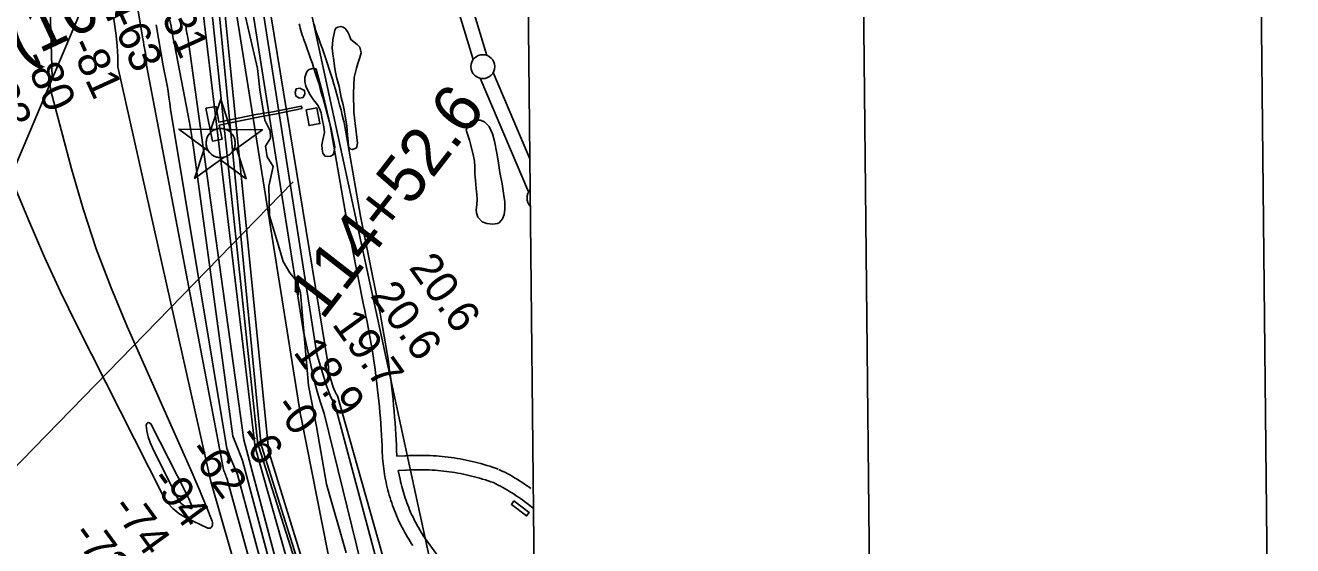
# Model space of a CAD drawing. Extents: x 3625074 to 3663148, y 511451 to 537151.
# Drawn here: x 3659909 to 3662565, y 517810 to 518899 of the extents above; entities that cross this region are included whole.
import ezdxf

# ---------------------------------------------------------------- set-up
doc = ezdxf.new("R2010")
doc.units = 0
for name, color, linetype in [('G-ANNO-NPLT', 7, 'Continuous'), ('V-ANNO-SYMB', 7, 'Continuous'), ('V-BLDG-OTLN', 7, 'Continuous'), ('V-CHAN-DOCK', 7, 'Continuous'), ('V-CHAN-NAID', 7, 'Continuous'), ('V-GRID-FRAM', 7, 'Continuous'), ('V-RIVR-EDGE', 7, 'Continuous'), ('V-RIVR-RANG', 7, 'Continuous'), ('V-ROAD-CNTR', 7, 'Continuous'), ('V-SITE-VEGE', 7, 'Continuous'), ('V-SURV-IDEN', 7, 'Continuous'), ('V-SURV-LINE', 7, 'Continuous'), ('V-TOPO-DPTH', 7, 'Continuous'), ('V-TOPO-MAJR', 7, 'Continuous'), ('V-TOPO-MINR', 7, 'Continuous'), ('V-TOPO-WATR', 7, 'Continuous'), ('V-UTIL-LINE', 7, 'Continuous')]:
    doc.layers.add(name, color=color, linetype=linetype)

msp = doc.modelspace()

# ---------------------------------------------------------------- linework, layer by layer
at = {"layer": 'G-ANNO-NPLT'}
msp.add_lwpolyline([(3625900.3, 512034), (3662565.2, 512401.9), (3662322.6, 536567.4), (3625657.8, 536199.4)], close=True, dxfattribs=at)
at = {"layer": 'V-ANNO-SYMB'}
msp.add_lwpolyline([(3628644.1, 512686.6), (3661725.6, 513018.6), (3661495.6, 535934), (3628414.1, 535602), (3628644.1, 512686.6)], dxfattribs=at)
at = {"layer": 'V-BLDG-OTLN'}
for points in [[(3660491.7, 518748.4), (3660483, 518746.4), (3660476.1, 518751.4), (3660474.6, 518758.4), (3660476.9, 518766), (3660485, 518768), (3660494.1, 518763), (3660495.2, 518756)], [(3660520.3, 518726.6), (3660526.7, 518693.6), (3660504.2, 518689.3), (3660497.8, 518722.3)], [(3660933.4, 517903.4), (3660965.3, 517879.1), (3660959.8, 517871.9), (3660927.9, 517896.2)]]:
    msp.add_lwpolyline(points, close=True, dxfattribs=at)
at = {"layer": 'V-CHAN-DOCK'}
msp.add_lwpolyline([(3660489.7, 518724.9), (3660432.5, 518713.4), (3660408.1, 518709.1), (3660370, 518701.4), (3660315.7, 518689.9), (3660321.7, 518660.7), (3660301.5, 518656.9), (3660287.8, 518725.5), (3660309.3, 518729.2), (3660314.6, 518696.5), (3660392.7, 518712.3), (3660428.4, 518718.2), (3660487.5, 518730.2), (3660489.7, 518724.9)], dxfattribs=at)
at = {"layer": 'V-CHAN-NAID'}
for points in [[(3660307.8, 518681.3), (3660298.2, 518681.4), (3660319.3, 518744.9), (3660339.5, 518681.1), (3660330, 518681.2), (3660328.4, 518681.8), (3660326.3, 518682.4), (3660324.2, 518682.8), (3660322.2, 518683.1), (3660321, 518683.3), (3660319.5, 518683.3), (3660317.8, 518683.3), (3660316.4, 518683.3), (3660314.5, 518683.1), (3660313.1, 518682.8), (3660311.4, 518682.5), (3660309.8, 518682), (3660308.8, 518681.7)], [(3660307.8, 518681.3), (3660231.3, 518681.9), (3660292.9, 518636.5), (3660291.7, 518638.4), (3660290.9, 518640), (3660290.1, 518642), (3660289.4, 518644), (3660289, 518645.4), (3660288.7, 518647), (3660288.4, 518648.4), (3660288.2, 518650), (3660288.1, 518651.8), (3660288.1, 518653.3), (3660288.2, 518655.4), (3660288.4, 518657), (3660288.8, 518659.2), (3660289.3, 518661.2), (3660289.9, 518663.1), (3660290.6, 518664.7), (3660291.3, 518666.3), (3660292.1, 518667.9), (3660293.2, 518669.6), (3660294.2, 518671.1), (3660295.2, 518672.3), (3660296.2, 518673.5), (3660297.5, 518674.8), (3660298.5, 518675.8), (3660300.3, 518677.2), (3660301.5, 518678), (3660303.2, 518679.1), (3660304.9, 518680.1), (3660306.3, 518680.7)], [(3660330, 518681.2), (3660406.4, 518680.6), (3660344.2, 518636.1), (3660345.2, 518637.6), (3660346.1, 518639.5), (3660346.8, 518641), (3660347.6, 518643), (3660348.1, 518644.8), (3660348.5, 518646.4), (3660348.9, 518648.4), (3660349.1, 518650), (3660349.2, 518652.2), (3660349.2, 518654.3), (3660349, 518656.5), (3660348.7, 518658.2), (3660348.2, 518660.5), (3660347.6, 518662.6), (3660346.8, 518664.6), (3660346.2, 518666), (3660345.2, 518668), (3660344.1, 518669.7), (3660342.9, 518671.4), (3660341.6, 518672.9), (3660340.4, 518674.3), (3660338.7, 518675.8), (3660337, 518677.2), (3660335.3, 518678.4), (3660333.4, 518679.5), (3660332, 518680.3)], [(3660326.2, 518623.2), (3660264, 518578.7), (3660285.1, 518642.2), (3660292.9, 518636.5), (3660293.5, 518635.5), (3660294.9, 518633.7), (3660296.1, 518632.2), (3660297.5, 518630.7), (3660298.9, 518629.5), (3660300.4, 518628.3), (3660301.8, 518627.3), (3660303.5, 518626.3), (3660305.2, 518625.4), (3660307, 518624.6), (3660308.4, 518624), (3660310.1, 518623.5), (3660312.3, 518622.9), (3660313.8, 518622.7), (3660315.8, 518622.4), (3660317.4, 518622.3), (3660319.2, 518622.3), (3660320.9, 518622.3), (3660322.6, 518622.5), (3660324.5, 518622.8)], [(3660344.2, 518636.1), (3660352, 518641.7), (3660372.3, 518577.9), (3660318.4, 518617.6), (3660326.2, 518623.2), (3660327.9, 518623.7), (3660329.5, 518624.2), (3660331.6, 518625.2), (3660333.4, 518626), (3660335.2, 518627.2), (3660337, 518628.4), (3660338.5, 518629.6), (3660339.8, 518630.8), (3660341.2, 518632.2), (3660342.4, 518633.6), (3660343.5, 518635.1)]]:
    msp.add_lwpolyline(points, close=True, dxfattribs=at)
msp.add_circle((3660318.7, 518652.8), 30.5, dxfattribs=at)
at = {"layer": 'V-GRID-FRAM'}
msp.add_lwpolyline([(3629129.4, 535042.1), (3660791.6, 535359.9), (3660982, 517178), (3629304, 516860), (3629129.4, 535042.1)], dxfattribs=at)
at = {"layer": 'V-RIVR-EDGE'}
msp.add_lwpolyline([(3660581.5, 517795), (3660540.2, 517938.5), (3660519.7, 518059.3), (3660502.7, 518145.1), (3660495.6, 518226), (3660486, 518339.4), (3660477.5, 518364.5), (3660463.5, 518381.1), (3660449.4, 518405), (3660437.9, 518445.5), (3660420.9, 518500.1), (3660419.8, 518562.6), (3660429.1, 518603.6), (3660416.3, 518623.9), (3660412.6, 518645.9), (3660423.1, 518663), (3660422.5, 518678.4), (3660411.6, 518700.5), (3660400.7, 518764.2), (3660395.9, 518808.9), (3660368.6, 518926)], dxfattribs=at)
at = {"layer": 'V-ROAD-CNTR'}
for points in [[(3660483.3, 518902.6), (3660484.5, 518897.8), (3660485.7, 518893.1), (3660487, 518888.3), (3660488.3, 518883.6), (3660489.8, 518878.9), (3660491.3, 518874.3), (3660492.4, 518871.2)], [(3660514.7, 518900.7), (3660515.8, 518896.5), (3660517.1, 518892.2), (3660518.4, 518888), (3660519.7, 518883.8), (3660520.7, 518880.9)], [(3660520.6, 518881.3), (3660524.5, 518870.9), (3660528.3, 518860.5), (3660532, 518850), (3660535.7, 518839.5), (3660539.3, 518828.9), (3660542.8, 518818.3), (3660546.2, 518807.8), (3660549.6, 518797.1), (3660552.9, 518786.5), (3660556.1, 518775.8), (3660559.2, 518765.1), (3660562.3, 518754.4), (3660565.2, 518743.7), (3660568.1, 518732.9), (3660571, 518722.2), (3660573.7, 518711.4), (3660576.4, 518700.6), (3660577.3, 518696.6)], [(3660492.5, 518870.8), (3660496.3, 518860.5), (3660500.1, 518850.3), (3660503.7, 518840), (3660507.3, 518829.7), (3660510.9, 518819.3), (3660514.3, 518809), (3660517.7, 518798.6), (3660521, 518788.2), (3660524.2, 518777.8), (3660527.3, 518767.3), (3660530.4, 518756.8), (3660533.4, 518746.3), (3660536.3, 518735.8), (3660539.1, 518725.3), (3660541.9, 518714.7), (3660544.6, 518704.1), (3660547.2, 518693.5), (3660548.1, 518689.6)], [(3660548, 518690.5), (3660582.3, 518494.4), (3660618.3, 518314)], [(3660577.5, 518695.7), (3660611.8, 518500), (3660647.8, 518319.9)], [(3660618.4, 518313.8), (3660620.9, 518302.1), (3660623.3, 518290.3), (3660625.6, 518278.6), (3660627.9, 518266.8), (3660630.1, 518255), (3660632.2, 518243.2), (3660634.2, 518231.4), (3660636.2, 518219.5), (3660638, 518207.7), (3660639.8, 518195.8), (3660641.5, 518184), (3660643.2, 518172.1), (3660644.7, 518160.2), (3660646.2, 518148.3), (3660647.6, 518136.4), (3660648.9, 518124.5), (3660650.2, 518112.5), (3660651.3, 518100.6), (3660652.4, 518088.7), (3660653.4, 518076.7), (3660654.3, 518064.8), (3660655.2, 518052.8), (3660656, 518040.8), (3660656.6, 518028.8), (3660657.1, 518020.2)], [(3660647.7, 518320.1), (3660650.2, 518308.2), (3660652.7, 518296.3), (3660655.1, 518284.3), (3660657.4, 518272.3), (3660659.6, 518260.4), (3660661.7, 518248.4), (3660663.8, 518236.3), (3660665.8, 518224.3), (3660667.7, 518212.3), (3660669.5, 518200.2), (3660671.2, 518188.2), (3660672.9, 518176.1), (3660674.5, 518164), (3660676, 518151.9), (3660677.4, 518139.8), (3660678.8, 518127.7), (3660680, 518115.5), (3660681.2, 518103.4), (3660682.3, 518091.3), (3660683.3, 518079.1), (3660684.3, 518067), (3660685.1, 518054.8), (3660685.9, 518042.6), (3660686.6, 518030.5), (3660687.1, 518021.7)], [(3660657.1, 518020.8), (3660657.1, 518015.3), (3660657.3, 518009.7), (3660657.5, 518004.1), (3660657.8, 517998.5), (3660658.1, 517992.8), (3660658.6, 517987.2), (3660659.2, 517981.6), (3660659.8, 517976), (3660660.5, 517970.5), (3660661.3, 517964.9), (3660662.2, 517959.3), (3660663.1, 517953.8), (3660664.2, 517948.3), (3660665.3, 517942.8), (3660666.5, 517937.3), (3660667.8, 517931.8), (3660669.2, 517926.3), (3660670.6, 517920.9), (3660672.1, 517915.5), (3660673.7, 517910.1), (3660675.4, 517904.7), (3660677.2, 517899.4), (3660679, 517894.1), (3660681, 517888.8), (3660683, 517883.5), (3660685, 517878.3), (3660687.2, 517873.1), (3660689.4, 517867.9), (3660691.7, 517862.8), (3660694.1, 517857.7), (3660696.6, 517852.6), (3660699.1, 517847.6), (3660701.7, 517842.6), (3660704.4, 517837.7), (3660707.2, 517832.8), (3660710, 517827.9), (3660712.9, 517823.1), (3660715.9, 517818.3), (3660718.9, 517813.6), (3660721.2, 517810.1)], [(3660687.1, 518021.1), (3660687.1, 518015.8), (3660687.2, 518010.6), (3660687.8, 517997.1)], [(3660900.5, 517970), (3660894.6, 517972.1), (3660888.6, 517974.1), (3660882.5, 517976.1), (3660876.4, 517977.9), (3660870.3, 517979.7), (3660864.2, 517981.5), (3660858, 517983.1), (3660851.8, 517984.7), (3660845.6, 517986.2), (3660839.4, 517987.6), (3660833.2, 517988.9), (3660827, 517990.1), (3660820.7, 517991.3), (3660814.4, 517992.4), (3660808.1, 517993.4), (3660801.8, 517994.3), (3660795.5, 517995.1), (3660789.2, 517995.9), (3660782.9, 517996.5), (3660776.5, 517997.1), (3660770.2, 517997.6), (3660763.8, 517998), (3660757.5, 517998.4), (3660751.1, 517998.6), (3660744.7, 517998.8), (3660738.4, 517998.9), (3660732, 517998.9), (3660725.6, 517998.9), (3660719.3, 517998.7), (3660712.9, 517998.5), (3660706.6, 517998.1), (3660687.8, 517997.1)], [(3660705.9, 517998.1), (3660705, 517998.1)], [(3660890.5, 517941.7), (3660884.8, 517943.7), (3660879.1, 517945.6), (3660873.5, 517947.5), (3660867.7, 517949.2), (3660862, 517950.9), (3660856.2, 517952.5), (3660850.5, 517954.1), (3660844.7, 517955.5), (3660838.9, 517956.9), (3660833, 517958.3), (3660827.2, 517959.5), (3660821.3, 517960.7), (3660815.4, 517961.7), (3660809.5, 517962.8), (3660803.6, 517963.7), (3660797.7, 517964.6), (3660791.8, 517965.3), (3660785.8, 517966), (3660779.9, 517966.7), (3660773.9, 517967.2), (3660768, 517967.7), (3660762, 517968.1), (3660756, 517968.4), (3660750.1, 517968.7), (3660744.1, 517968.8), (3660738.1, 517968.9), (3660732.1, 517968.9), (3660726.1, 517968.9), (3660720.2, 517968.7), (3660714.2, 517968.5), (3660708.2, 517968.2), (3660690.9, 517967.2)], [(3660706.3, 517968.1), (3660704.9, 517968.1)], [(3660969, 517929.6), (3660964.7, 517932.7), (3660959.8, 517936.1), (3660954.9, 517939.4), (3660949.9, 517942.7), (3660944.9, 517945.8), (3660939.9, 517949), (3660934.8, 517952), (3660929.6, 517955), (3660924.4, 517957.9), (3660919.2, 517960.7), (3660914, 517963.4), (3660908.7, 517966.1), (3660903.4, 517968.7), (3660902, 517969.4)], [(3660690.9, 517967.2), (3660694.6, 517949), (3660695.8, 517943.9), (3660696.9, 517938.9), (3660698.2, 517933.8), (3660699.5, 517928.8), (3660700.9, 517923.8), (3660702.4, 517918.9), (3660704, 517913.9), (3660705.6, 517909), (3660707.3, 517904.1), (3660709.1, 517899.2), (3660710.9, 517894.4), (3660712.8, 517889.6), (3660714.8, 517884.8), (3660716.9, 517880), (3660719, 517875.3), (3660721.2, 517870.6), (3660723.5, 517866), (3660725.8, 517861.3), (3660728.2, 517856.7), (3660730.7, 517852.2), (3660733.2, 517847.7), (3660735.8, 517843.2), (3660738.5, 517838.8), (3660741.2, 517834.4), (3660744, 517830), (3660746.2, 517826.7)], [(3660972.9, 517888.9), (3660960.7, 517898.4), (3660956.3, 517901.7), (3660951.9, 517905), (3660947.4, 517908.2), (3660942.9, 517911.3), (3660938.3, 517914.4), (3660933.7, 517917.4), (3660929, 517920.4), (3660924.3, 517923.3), (3660919.6, 517926.1), (3660914.8, 517928.9), (3660910, 517931.6), (3660905.1, 517934.2), (3660900.2, 517936.8), (3660895.3, 517939.3), (3660890.3, 517941.7), (3660889.1, 517942.3)], [(3660745.8, 517827.2), (3660806.8, 517743.4)]]:
    msp.add_lwpolyline(points, dxfattribs=at)
at = {"layer": 'V-SITE-VEGE'}
for points in [[(3660557.7, 518889.4), (3660559.9, 518893.1), (3660564.3, 518895.2), (3660570.8, 518896.7), (3660575.6, 518895.5), (3660579.9, 518892.8), (3660584.6, 518886.2), (3660588.2, 518879.1), (3660591.8, 518869.4), (3660604.6, 518859.4), (3660610.4, 518853.4), (3660612.4, 518844.7), (3660612.9, 518841.5), (3660610.1, 518831.8), (3660606.1, 518819), (3660603.2, 518809.3), (3660600.8, 518798.6), (3660598.5, 518790), (3660597.4, 518757.1), (3660597.8, 518717.7), (3660605.8, 518652.3), (3660604.1, 518645.4), (3660604, 518643.2), (3660600.8, 518641.1), (3660596.4, 518640.1), (3660594.8, 518639), (3660591, 518639.7), (3660586.3, 518644.6), (3660586.3, 518646.2), (3660585.9, 518657), (3660584.5, 518669.4), (3660583.3, 518688.3), (3660577.4, 518722.4), (3660575.4, 518732.7), (3660571.4, 518747.9), (3660566.9, 518771.1), (3660561.3, 518790.6), (3660558.4, 518804.7), (3660557.4, 518813.4), (3660556, 518825.8), (3660554.1, 518839.3), (3660552.7, 518851.2), (3660554.1, 518869)], [(3660502.3, 518805.2), (3660503.9, 518806.8), (3660514.2, 518809.3), (3660519, 518807.6), (3660533.7, 518752.8), (3660550.7, 518678.7), (3660558.2, 518644.5), (3660556.4, 518634.9), (3660554.2, 518628.4), (3660549.8, 518625.3), (3660543.3, 518624.9), (3660537.4, 518625), (3660533.2, 518630.4), (3660532.6, 518631.5), (3660531.2, 518640.2), (3660530.8, 518649.3), (3660532.6, 518659.6), (3660536.6, 518674.6), (3660535.2, 518687), (3660531.8, 518703.8), (3660529.3, 518715.7), (3660525.7, 518724.9), (3660521.5, 518732.6), (3660513.6, 518743.5), (3660505.2, 518755.5), (3660497.4, 518771.8), (3660494.8, 518781.6), (3660495, 518789.7), (3660497.8, 518798.2), (3660499, 518802)], [(3660833.8, 518677.4), (3660833.3, 518679.6), (3660833.9, 518681.7), (3660836.8, 518690.3), (3660842.8, 518697.2), (3660852, 518700.8), (3660862.3, 518700.7), (3660871.4, 518697.3), (3660881.5, 518687.4), (3660888.2, 518672.2), (3660892.3, 518657), (3660897.2, 518631.5), (3660900.1, 518615.3), (3660904, 518591), (3660908.5, 518567.2), (3660912.3, 518542.8), (3660914.3, 518529.9), (3660914, 518513.7), (3660912.7, 518502.9), (3660909.3, 518493.8), (3660902.2, 518485.8), (3660898.9, 518484.3), (3660889.2, 518482.8), (3660876.8, 518484.1), (3660866.6, 518487.6), (3660857.6, 518497.4), (3660855.1, 518506.6), (3660854.1, 518513.1), (3660855.4, 518523.3), (3660856.1, 518535.2), (3660855.8, 518544.9), (3660854.4, 518557.3), (3660853, 518574.6), (3660851.7, 518588.1), (3660851.4, 518603.2), (3660850.5, 518615.1), (3660848.6, 518625.4), (3660846.1, 518637.3), (3660840.5, 518659)]]:
    msp.add_lwpolyline(points, close=True, dxfattribs=at)
at = {"layer": 'V-SURV-LINE'}
for points in [[(3660848, 518827.5), (3660727.3, 519226.5)], [(3660756, 519235.2), (3660876.7, 518836.2)], [(3660889.8, 518800.2), (3660966.9, 518619.9)], [(3660964, 518550.4), (3660862.2, 518788.4)]]:
    msp.add_lwpolyline(points, dxfattribs=at)
msp.add_circle((3660868.1, 518812.7), 25, dxfattribs=at)
msp.add_arc((3660985.7, 518537.9), 25, 136.255, 224.945, dxfattribs=at)
at = {"layer": 'V-TOPO-DPTH'}
for points in [[(3660592.1, 517304.9), (3660391.1, 518016), (3660277.2, 518966.5)], [(3660592.1, 517304.9), (3660391.1, 518016), (3660277.2, 518966.5)], [(3660403.7, 518955.4), (3660519.5, 518215.4), (3660521.3, 518208.3), (3660539.9, 518146.7), (3660543.7, 518135.5), (3660548.1, 518124.4), (3660553.2, 518113.7), (3660558.8, 518103.2), (3660704.1, 517560.6)], [(3660562, 517246.4), (3660364.8, 517988.4), (3660354.5, 518013.5), (3660344.5, 518038.7), (3660261.5, 518643.5), (3660258.2, 518665.9), (3660254.5, 518688.2), (3660250.4, 518710.4), (3660221.8, 518858.8), (3660219.4, 518871.7), (3660217, 518884.5), (3660214.7, 518897.4), (3660212.5, 518910.3)], [(3660212.5, 518910.3), (3660214.7, 518897.4), (3660217, 518884.5), (3660219.4, 518871.7), (3660221.8, 518858.8), (3660250.4, 518710.4), (3660254.5, 518688.2), (3660258.2, 518665.9), (3660261.5, 518643.5), (3660344.5, 518038.7), (3660354.5, 518013.5), (3660364.8, 517988.4), (3660562, 517246.4)], [(3660245.3, 518901.3), (3660245.7, 518897.6), (3660246.3, 518893.9), (3660246.8, 518890.2), (3660247.3, 518887.2), (3660248.1, 518882.8), (3660248.5, 518880.6), (3660249.4, 518876.3), (3660249.8, 518874.1), (3660250.7, 518869.8), (3660367.6, 518031.1), (3660576.1, 517247.5)], [(3660245.3, 518901.3), (3660245.7, 518897.6), (3660246.3, 518893.9), (3660246.8, 518890.2), (3660247.3, 518887.2), (3660248.1, 518882.8), (3660248.5, 518880.6), (3660249.4, 518876.3), (3660249.8, 518874.1), (3660250.7, 518869.8), (3660367.6, 518031.1), (3660576.1, 517247.5)], [(3660316.5, 518919.2), (3660403.9, 518019.1), (3660404.9, 518016.9), (3660624.7, 517318.8)], [(3660624.7, 517318.8), (3660404.9, 518016.9), (3660403.9, 518019.1), (3660316.5, 518919.2)], [(3660352.8, 518918.8), (3660486.8, 518079.7), (3660487.2, 518077.9), (3660632.6, 517342.9)], [(3660632.6, 517342.9), (3660487.2, 518077.9), (3660486.8, 518079.7), (3660352.8, 518918.8)]]:
    msp.add_lwpolyline(points, dxfattribs=at)
at = {"layer": 'V-TOPO-MAJR'}
msp.add_lwpolyline([(3660544.9, 517245.3), (3660354, 517958.5), (3660346.4, 517976.7), (3660339, 517995.1), (3660331.9, 518013.5), (3660213.8, 518723.9), (3660212.2, 518736.3), (3660210.4, 518748.7), (3660208.4, 518761.1), (3660206.3, 518773.5), (3660198.6, 518814.6), (3660193.4, 518843.1), (3660188.4, 518871.5), (3660183.5, 518900)], dxfattribs=at)
at = {"layer": 'V-TOPO-MINR'}
for points in [[(3659887.7, 518560.4), (3659918, 518486.8), (3659949.6, 518413.7), (3659983.3, 518341.5), (3660018.3, 518269.9), (3660198.5, 517913.9), (3660207.6, 517899.8), (3660218.2, 517887.3), (3660231, 517877.1), (3660245.4, 517868.5), (3660292.1, 517846.7), (3660294.6, 517846.3), (3660296.8, 517846.5), (3660298.7, 517847.8), (3660300.3, 517849.7), (3660301.3, 517852.5), (3660301.7, 517855.3), (3660301.5, 517858.1), (3660300.7, 517860.9), (3660288.8, 517891), (3660281.6, 517908.9), (3660274.2, 517926.7), (3660266.6, 517944.4), (3660258.9, 517962), (3660122.7, 518268.7), (3660089, 518349.7), (3660058, 518431.5), (3660030.9, 518514.8), (3660006.4, 518599), (3659963.1, 518762.3), (3659962.4, 518765.5), (3659961.9, 518768.8), (3659961.8, 518772), (3659961.8, 518775.3), (3659962.2, 518783.7), (3659962.6, 518786.8), (3659963.2, 518788.6), (3659963.8, 518789.3), (3659965.4, 518789.9), (3659944.9, 519502.1)], [(3660531.9, 517222.8), (3660332.5, 517948.8), (3660331.6, 517951.4), (3660330.6, 517953.9), (3660329.6, 517956.5), (3660328.6, 517959.1), (3660327.6, 517961.6), (3660326.6, 517964.2), (3660325.6, 517966.8), (3660324.6, 517969.3), (3660163.4, 518815.8), (3660163.5, 518818.4), (3660163.6, 518821.1), (3660163.5, 518823.7), (3660163.3, 518826.3), (3660163, 518829), (3660162.6, 518831.6), (3660162.2, 518834.2), (3660161.7, 518836.8), (3660160.3, 518844.7), (3660159.2, 518851.3), (3660158, 518857.8), (3660156.9, 518864.4), (3660155.8, 518870.9), (3660098.7, 519213.4)], [(3660806.7, 517551.8), (3660493.9, 518995.4)], [(3660592.1, 517304.9), (3660391.1, 518016), (3660277.2, 518966.5)], [(3660700.4, 517416.1), (3660535.9, 518086.3), (3660527.7, 518109.2), (3660520.8, 518132.5), (3660514.8, 518156.1), (3660494.9, 518245.7), (3660492.6, 518257.7), (3660381, 518958.7)], [(3660704.1, 517560.6), (3660558.8, 518103.2), (3660553.2, 518113.7), (3660548.1, 518124.4), (3660543.7, 518135.5), (3660539.9, 518146.7), (3660521.3, 518208.3), (3660519.5, 518215.4), (3660403.7, 518955.4)], [(3660726, 517547.4), (3660563.7, 518123.3), (3660560.9, 518127.7), (3660558.5, 518132.2), (3660556.5, 518136.9), (3660554.7, 518141.7), (3660546.2, 518169.3), (3660545.5, 518172.3), (3660545, 518175.2), (3660544.7, 518178.2), (3660544.7, 518181.3), (3660544.9, 518184.3), (3660417.1, 518964.6)], [(3660519.9, 517173.3), (3660298.2, 517944.1), (3660103, 518812.1), (3660103.3, 518834.2), (3660102, 518856.2), (3660099.7, 518878.2), (3660090, 518946.9)], [(3660629.1, 517328.5), (3660421.3, 518001.9), (3660418.8, 518006.9), (3660418.4, 518009.2), (3660418.6, 518011.1), (3660418.7, 518011.7), (3660327.3, 518927.2)], [(3660562, 517246.4), (3660364.8, 517988.4), (3660354.5, 518013.5), (3660344.5, 518038.7), (3660261.5, 518643.5), (3660258.2, 518665.9), (3660254.5, 518688.2), (3660250.4, 518710.4), (3660221.8, 518858.8), (3660219.4, 518871.7), (3660217, 518884.5), (3660214.7, 518897.4), (3660212.5, 518910.3)], [(3660576.1, 517247.5), (3660367.6, 518031.1), (3660250.7, 518869.8), (3660249.8, 518874.1), (3660249.4, 518876.3), (3660248.5, 518880.6), (3660248.1, 518882.8), (3660247.3, 518887.2), (3660246.8, 518890.2), (3660246.3, 518893.9), (3660245.7, 518897.6), (3660245.3, 518901.3)], [(3660626.6, 517300.6), (3660398.5, 518016.5), (3660396.3, 518021.6), (3660301, 518922.5)], [(3660624.7, 517318.8), (3660404.9, 518016.9), (3660403.9, 518019.1), (3660316.5, 518919.2)], [(3660235.3, 517898.8), (3660239, 517895.9), (3660243.1, 517893.5), (3660256.3, 517887.3), (3660257.6, 517887.2), (3660258.6, 517888.1), (3660258.9, 517890.5), (3660258.7, 517891.3), (3660255.3, 517899.8), (3660253.2, 517904.9), (3660251.1, 517909.9), (3660248.7, 517914.8), (3660246.3, 517919.7), (3660172.1, 518065.1), (3660168.9, 518067.2), (3660166.2, 518067.7), (3660164.1, 518065.9), (3660162.4, 518062.4), (3660164.1, 518049.9), (3660166.8, 518037.7), (3660170.8, 518025.9), (3660175.8, 518014.3), (3660229.8, 517906.4), (3660232.3, 517902.3), (3660235.3, 517898.8)]]:
    msp.add_lwpolyline(points, dxfattribs=at)
at = {"layer": 'V-TOPO-WATR'}
msp.add_lwpolyline([(3660632.6, 517342.9), (3660487.2, 518077.9), (3660486.8, 518079.7), (3660352.8, 518918.8)], dxfattribs=at)
at = {"layer": 'V-UTIL-LINE'}
for p, q in [((3660309.8, 519601.1), (3659277, 517160.9)), ((3659093.3, 517159), (3660470.5, 518571.5))]:
    msp.add_line(p, q, dxfattribs=at)

# ---------------------------------------------------------------- texts
at = {"layer": 'V-CHAN-NAID'}
for s, p in [('AUDUBON PARK EXCURSION', (3658613.3, 518381.2)), ('BOAT LANDING (101.7)', (3658962.1, 518384.7))]:
    msp.add_text(s, height=100, rotation=24.9994, dxfattribs=at).set_placement(p)
at = {"layer": 'V-RIVR-RANG'}
for s, rotation, p in [('-31', 294.528, (3660182, 518943.3)), ('-63', 294.528, (3660085.3, 518914.3)), ('-81', 294.528, (3660000.9, 518858.3)), ('-80', 294.528, (3659903.7, 518830.5)), ('-83', 294.528, (3659811.7, 518791.4)), ('20.6', 305.7583, (3660711.5, 518392)), ('20.6', 305.7583, (3660630.5, 518333.4)), ('19.7', 305.7583, (3660550.6, 518273.3)), ('18.9', 305.7583, (3660469.4, 518214.8)), ('-0', 305.7583, (3660428.7, 518100.3)), ('-6', 306.0405, (3660353.6, 518037.5)), ('-62', 306.0405, (3660248.4, 518007.7)), ('-94', 306.0405, (3660169.1, 517946.8)), ('-74', 306.0405, (3660087.8, 517888.6)), ('-73', 306.0405, (3660004.7, 517832.7))]:
    msp.add_text(s, height=67, rotation=rotation, dxfattribs=at).set_placement(p)
at = {"layer": 'V-SURV-IDEN'}
msp.add_text('114+52.6', height=100, rotation=52.1821, dxfattribs=at).set_placement((3660531.7, 518279.9))

doc.saveas('drawing.dxf')
